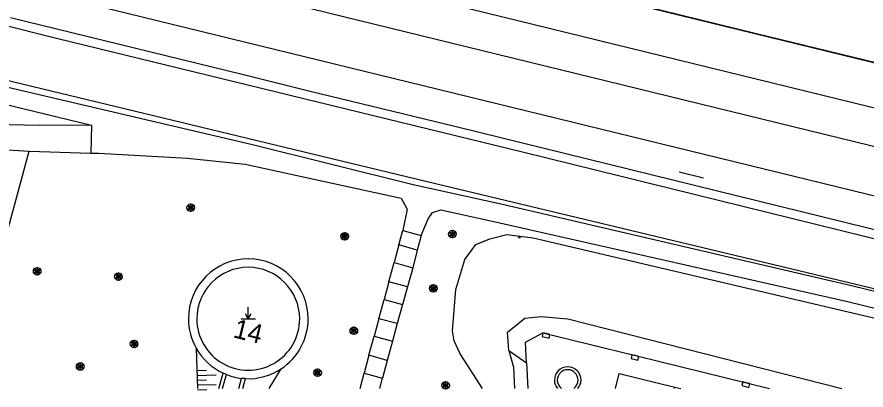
# Model space of a CAD drawing. Extents: x 132998 to 136004, y 396998 to 398512.
# Drawn here: x 133137.8 to 133226.6, y 396999.8 to 397038.8 of the extents above; entities that cross this region are included whole.
import ezdxf

# ---------------------------------------------------------------- set-up
doc = ezdxf.new("R2010")
doc.units = 0
for name, color, linetype in [('gg-afsc-hekwerk', 7, 'Continuous'), ('gg-afsc-muur', 7, 'Continuous'), ('gg-aspt-spoorlijn', 7, 'Continuous'), ('gg-knt-BGT kruinlijn', 7, 'Continuous'), ('gg-knt-bovenkant onderkant talud', 7, 'Continuous'), ('gg-knt-trap', 7, 'Continuous'), ('gg-knt-verharding', 7, 'Continuous'), ('gg-kntw-beschoeiing', 7, 'Continuous'), ('gg-kwrk-keermuur', 7, 'Continuous'), ('gt-afsc-standplaatsafbakening', 7, 'Continuous'), ('gt-anno-standplaatsnummer', 7, 'Continuous'), ('gt-grn-bladgrens', 7, 'Continuous'), ('gt-grn-groengrens', 7, 'Continuous'), ('gt-grn-vlakafsluiter', 7, 'Continuous'), ('gt-grn-weggrens', 7, 'Continuous'), ('gt-symb-kolk', 7, 'Continuous'), ('gt-symb-markant object', 7, 'Continuous'), ('gt-symb-solitaire heester', 7, 'Continuous'), ('gt-symb-talud symbool', 7, 'Continuous')]:
    doc.layers.add(name, color=color, linetype=linetype)

# ---------------------------------------------------------------- blocks, each defined once
blk = doc.blocks.new('gt0-KOLK')
at = {"layer": 'gt-symb-kolk'}
blk.add_lwpolyline([(0, 0), (0.375, 0), (0.375, 0.4), (-0.375, 0.4), (-0.375, 0), (0, 0)], dxfattribs=at)
blk = doc.blocks.new('gt0-SH')
at = {"layer": 'gt-symb-solitaire heester'}
blk.add_circle((0, 0), 0.4, dxfattribs=at)
for centre, start, end in [((-0.346, 0.2), 270, 30), ((-0.346, -0.2), 330, 90), ((0, 0.4), 210, 330), ((0.346, 0.2), 150, 270), ((0.346, -0.2), 90, 210), ((0, -0.4), 30, 150)]:
    blk.add_arc(centre, 0.4, start, end, dxfattribs=at)
blk = doc.blocks.new('gt0-TALUD_1')
at = {"layer": 'gt-symb-talud symbool'}
for p, q in [((-1, -1), (-1, 0)), ((-0.5, -2), (-0.5, 0)), ((0, -1), (0, 0)), ((0.5, -2), (0.5, 0)), ((1, -1), (1, 0))]:
    blk.add_line(p, q, dxfattribs=at)
blk = doc.blocks.new('gt0-MARKOB')
at = {"layer": 'gt-symb-markant object'}
for p, q in [((0, 0), (0, 1.2)), ((-0.75, 0), (0.75, 0)), ((0, 0), (-0.3, 0.52)), ((0, 0), (0.3, 0.52))]:
    blk.add_line(p, q, dxfattribs=at)

msp = doc.modelspace()

# ---------------------------------------------------------------- linework, layer by layer
at = {"layer": 'gg-afsc-hekwerk'}
msp.add_line((133207.065, 397022.665), (133209.628, 397022.017), dxfattribs=at)
msp.add_lwpolyline([(133000, 397065.503), (133076.543, 397046.781), (133180.571, 397021.692), (133271.17, 397000)], dxfattribs=at)
msp.add_lwpolyline([(133000, 397065.503), (133076.543, 397046.781), (133180.571, 397021.692), (133271.17, 397000)], dxfattribs=at)
at = {"layer": 'gg-afsc-muur'}
for p, q in [((133293.74, 397017.818), (133163.478, 397049.706)), ((133293.74, 397017.818), (133163.478, 397049.706)), ((133158.924, 397000), (133159.372, 397001.604)), ((133159.3, 397000), (133159.702, 397001.463)), ((133161.01, 397000), (133161.293, 397001.068)), ((133161.413, 397000), (133161.688, 397001.036))]:
    msp.add_line(p, q, dxfattribs=at)
for centre, radius, start, end in [((133195.42, 397000.886), 1.39, 0.04122, 180.04122), ((133195.415, 397000.882), 1.084, 0, 180), ((133195.416, 397000.885), 1.386, 179.98846, 219.65514), ((133195.414, 397000.881), 1.083, 179.96806, 234.50526), ((133195.416, 397000.881), 1.083, 305.49474, 0.03194), ((133195.418, 397000.887), 1.392, 320.42483, 0.01401)]:
    msp.add_arc(centre, radius, start, end, dxfattribs=at)
at = {"layer": 'gg-aspt-spoorlijn'}
msp.add_line((133000, 397081.027), (133298.474, 397007.929), dxfattribs=at)
for points in [[(133000, 397085.097), (133023.788, 397079.291), (133131.609, 397052.829), (133298.931, 397011.894)], [(133000, 397075.839), (133096.746, 397052.101), (133297.901, 397002.954)]]:
    msp.add_lwpolyline(points, dxfattribs=at)
at = {"layer": 'gg-knt-BGT kruinlijn'}
for p, q in [((133156.537, 397004.218), (133156.665, 397000)), ((133164.175, 397000), (133165.439, 397002.061))]:
    msp.add_line(p, q, dxfattribs=at)
msp.add_lwpolyline([(133186.49, 397000), (133184.153, 397003.644), (133183.522, 397004.975), (133183.374, 397006.047), (133183.716, 397010.358), (133184.658, 397013.497), (133185.793, 397015.048), (133187.27, 397015.648), (133189.046, 397016.11), (133191.787, 397015.743), (133224.019, 397008.202), (133258.747, 397000)], dxfattribs=at)
at = {"layer": 'gg-knt-bovenkant onderkant talud'}
for points in [[(133189.247, 397003.987), (133189.124, 397005.911), (133190.947, 397007.366), (133192.627, 397007.549), (133195.418, 397007.296), (133224.112, 397000)], [(133189.247, 397003.987), (133189.749, 397002.249), (133189.845, 397000)]]:
    msp.add_lwpolyline(points, dxfattribs=at)
at = {"layer": 'gg-knt-trap'}
for p, q in [((133177.751, 397015.021), (133178.172, 397016.523)), ((133178.172, 397016.523), (133180.087, 397016.001)), ((133180.087, 397016.001), (133179.673, 397014.478)), ((133179.673, 397014.478), (133177.751, 397015.021)), ((133176.711, 397011.164), (133177.253, 397013.167)), ((133177.253, 397013.167), (133179.197, 397012.638)), ((133179.197, 397012.638), (133178.642, 397010.637)), ((133178.642, 397010.637), (133176.711, 397011.164)), ((133175.658, 397007.301), (133176.215, 397009.318)), ((133176.215, 397009.318), (133178.133, 397008.802)), ((133178.133, 397008.802), (133177.59, 397006.796)), ((133177.59, 397006.796), (133175.658, 397007.301)), ((133174.625, 397003.474), (133175.173, 397005.473)), ((133175.173, 397005.473), (133177.091, 397004.958)), ((133177.091, 397004.958), (133176.531, 397002.946)), ((133176.531, 397002.946), (133174.625, 397003.474)), ((133173.689, 397000), (133174.129, 397001.613)), ((133174.129, 397001.613), (133176.055, 397001.099)), ((133175.754, 397000), (133176.055, 397001.099))]:
    msp.add_line(p, q, dxfattribs=at)
at = {"layer": 'gg-knt-verharding'}
for p, q in [((133139.06, 397024.831), (133145.518, 397024.622)), ((133177.751, 397015.021), (133177.253, 397013.167)), ((133179.673, 397014.478), (133179.197, 397012.638)), ((133176.711, 397011.164), (133176.215, 397009.318)), ((133178.642, 397010.637), (133178.133, 397008.802)), ((133175.658, 397007.301), (133175.173, 397005.473)), ((133177.59, 397006.796), (133177.091, 397004.958)), ((133174.625, 397003.474), (133174.129, 397001.613)), ((133176.531, 397002.946), (133176.055, 397001.099)), ((133191.12, 397002.689), (133191.263, 397000)), ((133206.593, 397000), (133206.631, 397000.152)), ((133206.631, 397000.152), (133207.252, 397000))]:
    msp.add_line(p, q, dxfattribs=at)
for points in [[(133000, 397064.614), (133037.586, 397055.47), (133127.872, 397033.617), (133162.421, 397025.507), (133179.236, 397021.338), (133188.591, 397019.265), (133225.122, 397010.768), (133269.223, 397000)], [(133055.497, 397048.912), (133126.722, 397032.091), (133145.605, 397027.536)], [(133145.605, 397027.536), (133140.153, 397027.487), (133135.428, 397027.603), (133118.923, 397028.335), (133068.746, 397031.25), (133061.128, 397032.266), (133050.184, 397035.054), (133034.262, 397038.825)], [(133074.504, 397027.882), (133074.861, 397028.615), (133076.862, 397028.719), (133139.06, 397024.831)], [(133145.518, 397024.622), (133146.337, 397024.595), (133155.647, 397024.086), (133161.652, 397023.448), (133177.975, 397019.906), (133178.609, 397018.77), (133178.172, 397016.523)], [(133180.087, 397016.001), (133180.812, 397017.737), (133181.256, 397018.408), (133182.146, 397018.674), (133187.675, 397017.479), (133224.542, 397009.119), (133261.83, 397000)], [(133191.12, 397002.689), (133191.005, 397004.858), (133192.813, 397005.828), (133202.504, 397003.439), (133216.547, 397000)], [(133200.428, 397000), (133200.815, 397001.576), (133206.631, 397000.152)]]:
    msp.add_lwpolyline(points, dxfattribs=at)
at = {"layer": 'gg-kntw-beschoeiing'}
msp.add_lwpolyline([(133293.908, 397017.321), (133294.015, 397017.844), (133281.102, 397020.96), (133261.323, 397025.845), (133257.889, 397026.669), (133240.574, 397030.918), (133215.176, 397037.087), (133173.826, 397047.249), (133156.339, 397051.485), (133065.484, 397073.822), (133055.258, 397076.278), (133002.984, 397089.089), (133000, 397089.82)], dxfattribs=at)
at = {"layer": 'gg-kwrk-keermuur'}
for p, q in [((133159.702, 397001.463), (133159.372, 397001.604)), ((133161.688, 397001.036), (133161.293, 397001.068))]:
    msp.add_line(p, q, dxfattribs=at)
for centre, radius, start, end in [((133161.995, 397007.293), 6.264, 0.01372, 180.01372), ((133162, 397007.293), 6.269, 180.0187, 209.37479), ((133161.986, 397007.297), 6.272, 303.40563, 359.97196), ((133161.987, 397007.284), 6.253, 209.36425, 245.2808), ((133161.978, 397007.227), 6.197, 248.45616, 263.65785), ((133161.99, 397007.305), 6.277, 267.23846, 303.32864)]:
    msp.add_arc(centre, radius, start, end, dxfattribs=at)
at = {"layer": 'gt-afsc-standplaatsafbakening'}
for start, end in [(359.98935, 179.98935), (179.98935, 359.98935)]:
    msp.add_arc((133161.994, 397007.295), 5.379, start, end, dxfattribs=at)
at = {"layer": 'gt-grn-bladgrens'}
for points in [[(133034.543, 397063.022), (133070.333, 397054.424), (133117.072, 397042.894), (133141.925, 397036.619), (133190.839, 397024.702), (133259.561, 397007.794), (133287.473, 397000.823), (133288.445, 397000.833), (133289.162, 397000.874), (133290.088, 397000.969), (133291.041, 397001.116), (133291.395, 397001.114), (133291.936, 397001.083), (133292.338, 397001.031), (133293.506, 397000.709), (133296.595, 397000)], [(133137.097, 397038.789), (133161.496, 397032.818), (133168.348, 397031.137), (133183.76, 397027.389), (133208.835, 397021.229), (133224.286, 397017.445), (133240.265, 397013.495), (133263.107, 397007.834), (133279.21, 397003.889), (133287.635, 397001.837), (133287.532, 397001.259), (133288.413, 397001.182), (133289.388, 397001.259), (133291.1, 397001.445), (133291.94, 397001.424), (133292.43, 397001.388), (133294.97, 397000.752), (133297.579, 397000.161)]]:
    msp.add_lwpolyline(points, dxfattribs=at)
at = {"layer": 'gt-grn-groengrens'}
msp.add_line((133189.247, 397003.987), (133191.12, 397002.689), dxfattribs=at)
at = {"layer": 'gt-grn-vlakafsluiter'}
msp.add_line((133132.316, 397000), (133139.06, 397024.831), dxfattribs=at)
at = {"layer": 'gt-grn-weggrens'}
msp.add_line((133145.605, 397027.536), (133145.518, 397024.622), dxfattribs=at)

# ---------------------------------------------------------------- block references
at = {"layer": 'gt-symb-kolk'}
for p, rotation in [((133193.195, 397005.739), 166.7858185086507), ((133202.504, 397003.439), 166.1222858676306), ((133214.105, 397000.601), 166.24561379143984)]:
    msp.add_blockref('gt0-KOLK', p, dxfattribs=dict(at, rotation=rotation))
at = {"layer": 'gt-symb-markant object'}
msp.add_blockref('gt0-MARKOB', (133161.994, 397007.294), dxfattribs=at)
at = {"layer": 'gt-symb-solitaire heester'}
for p in [(133155.98, 397018.902), (133183.359, 397016.144), (133172.083, 397015.91), (133139.904, 397012.263), (133148.402, 397011.708), (133181.356, 397010.469), (133173.039, 397006.04), (133150.041, 397004.667), (133144.406, 397002.305), (133169.246, 397001.655), (133182.639, 397000.325)]:
    msp.add_blockref('gt0-SH', p, dxfattribs=at)
at = {"layer": 'gt-symb-talud symbool'}
for p, xscale, yscale, rotation in [((133190.398, 397015.929), 0.09984988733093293, 0.09984988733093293, -7.480886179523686), ((133156.64, 397000.847), 0.9993647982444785, 0.9993647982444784, 91.54815769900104)]:
    msp.add_blockref('gt0-TALUD_1', p, dxfattribs=dict(at, xscale=xscale, yscale=yscale, rotation=rotation))

# ---------------------------------------------------------------- texts
at = {"layer": 'gt-anno-standplaatsnummer'}
msp.add_text('14', height=2, rotation=346.05574, dxfattribs=at).set_placement((133160.317, 397005.376))

doc.saveas('drawing.dxf')
